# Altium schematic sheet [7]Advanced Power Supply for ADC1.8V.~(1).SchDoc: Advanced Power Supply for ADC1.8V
size A4; Organization: BQR; Address1: Reliability Engineering; Address2: Optimized Maintenance; Address3: www.bqr.com; Address4: www.bqr-digital.com; DocumentNumber: DOC8; SheetNumber: 13; SheetTotal: 13
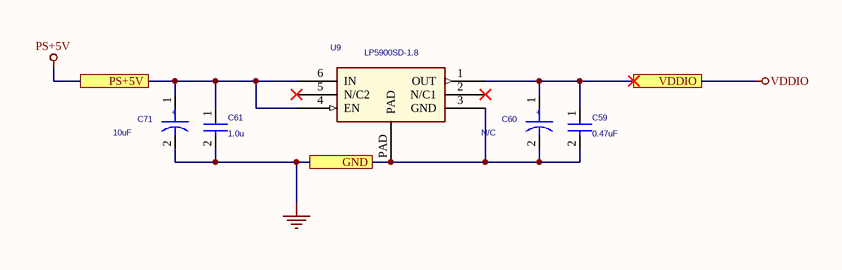
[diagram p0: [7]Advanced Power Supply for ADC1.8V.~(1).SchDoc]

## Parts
C59  0.47uF  [0603]
C60  N/C  [cap_c-case]
C61  1.0u  [0603]
C71  10uF  [cap_c-case]
U9  LP5900SD-1.8  [lp5900_sdb06a-llp6]

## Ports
GND, PS+5V, VDDIO

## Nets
GND: C59.2 C60.2 C61.2 C71.2 U9.3(GND) U9.PAD ; port GND
PS+5V: C61.1 C71.1 U9.4(EN) U9.6(IN) ; port PS+5V
VDDIO: C59.1 C60.1 U9.1(OUT) ; port VDDIO

Not connected (* = marked no-connect by the designer): U9 2(N/C1)* 5(N/C2)*

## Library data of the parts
C59 = Capacitor_3: CAP CER 0.47UF 6.3V X5R 0603; Manufacturer P/N: ECJ-1VB0J474K; Manufacturer: Panasonic; fiX_Manuf: AVX; Catalog Number: CAP00016; SDTA_V(Voltage): 1.8; fiX_Func: Advanced Power Supply for ADC 1.8V (7)
C60 = Cap_Polar_1: CAP TANT 10UF 20V 10% 2312; Manufacturer P/N: TAJC106K020R; Manufacturer: AVX; fiX_Manuf: Murata; Catalog Number: CAP00001; SDTA_I(Isurge): 0.01; SDTA_Par5(Vrev): 0.001; SDTA_V(Voltage): 1.8; fiX_Func: Advanced Power Supply for ADC 1.8V (7)
C61 = Capacitor_3: CAP CER 1UF 16V X7R 0603; Manufacturer P/N: GRM188R71C105KA12D; Manufacturer: Murata; fiX_Manuf: AVX; Catalog Number: CAP00028; SDTA_V(Voltage): 5; fiX_Func: Advanced Power Supply for ADC 1.8V (7)
C71 = Cap_Polar_1: CAP TANT 10UF 20V 10% 2312; Manufacturer P/N: TAJC106K020R; Manufacturer: AVX; fiX_Manuf: Murata; Catalog Number: CAP00001; SDTA_I(Isurge): 0.001; SDTA_V(Voltage): 5; fiX_Func: Advanced Power Supply for ADC 1.8V (7)
U9 = LP5900SD-1_0.8: IC REG LDO 1.8V 0.15A 6WSON; Manufacturer: Texas Instruments; Manufacturer P/N: LP5900SD-1.8/NOPB; Catalog Number: IC00031; fiX_Func: Advanced Power Supply for ADC 1.8V (7)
